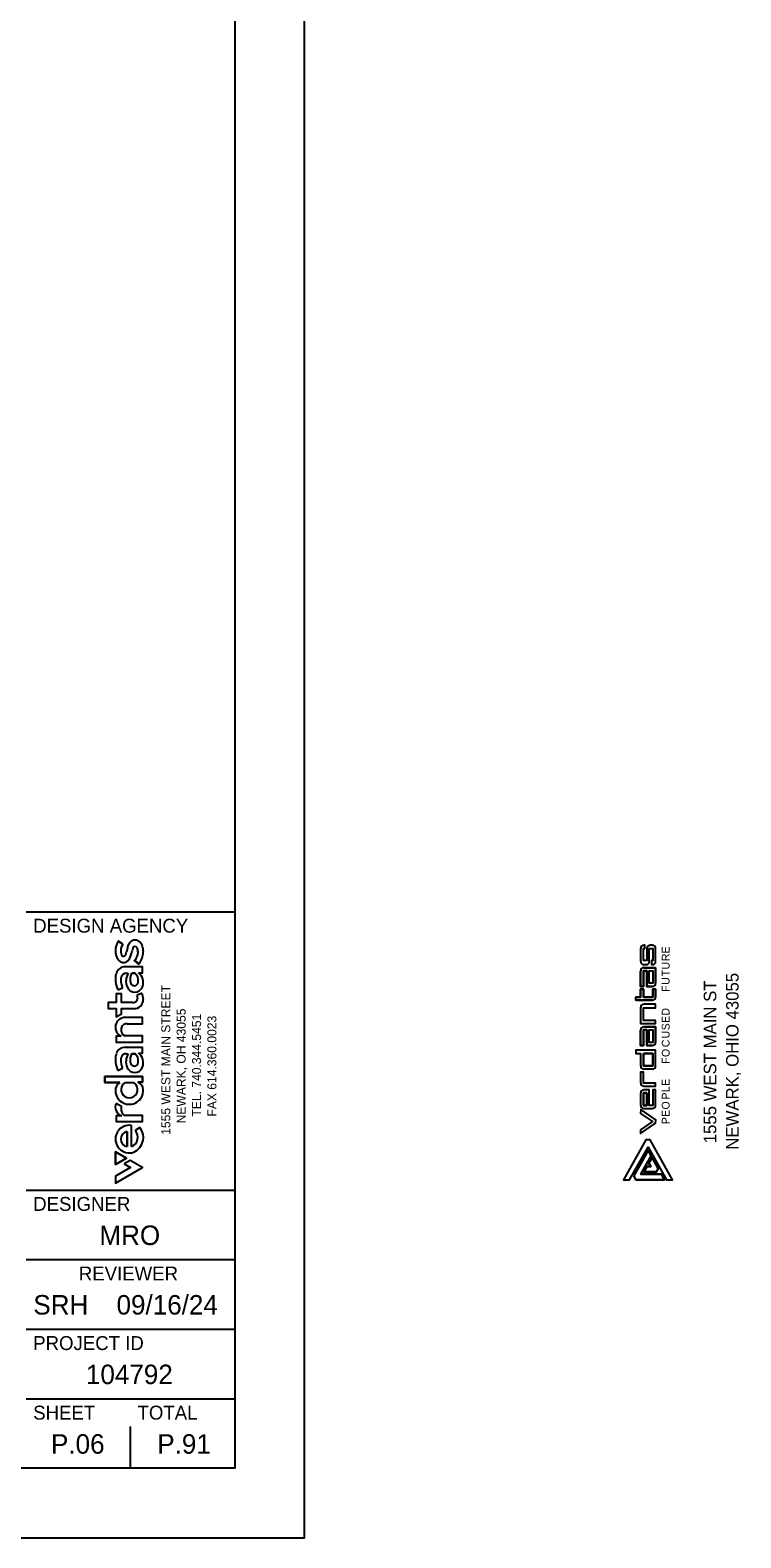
# Model space of a CAD drawing. Extents: x 0 to 37.1, y 0 to 22.
# Drawn here: x 32.03 to 37.14, y 0 to 10.84 of the extents above; entities that cross this region are included whole.
import ezdxf

# ---------------------------------------------------------------- set-up
doc = ezdxf.new("R2010")
doc.units = 0
for name, color, linetype in [('CS-ANNO-TTLB-LOGO', 7, 'Continuous'), ('Default', 7, 'Continuous'), ('SH_Border', 7, 'Continuous'), ('SH_Cut_Line', 7, 'Continuous'), ('SH_Data', 7, 'Continuous'), ('SH_Text', 7, 'Continuous')]:
    doc.layers.add(name, color=color, linetype=linetype)

msp = doc.modelspace()

# ---------------------------------------------------------------- linework, layer by layer
at = {"layer": 'CS-ANNO-TTLB-LOGO'}
for p, q in [((36.417, 4.236), (36.417, 4.143)), ((36.448, 4.259), (36.44, 4.259)), ((36.502, 4.259), (36.485, 4.259)), ((36.524, 4.143), (36.524, 4.236)), ((36.44, 4.121), (36.457, 4.121)), ((36.417, 3.963), (36.417, 4.076)), ((36.417, 3.539), (36.417, 3.651)), ((36.44, 3.37), (36.502, 3.37)), ((36.417, 3.198), (36.417, 3.108)), ((36.524, 3.108), (36.524, 3.221)), ((36.44, 3.086), (36.502, 3.086))]:
    msp.add_line(p, q, dxfattribs=at)
for points in [[(36.462, 4.236), (36.462, 4.149), (36.437, 4.149), (36.437, 4.236), (36.448, 4.236), (36.448, 4.259)], [(36.479, 4.143), (36.479, 4.236), (36.504, 4.236), (36.504, 4.149), (36.496, 4.149), (36.496, 4.121), (36.502, 4.121)], [(36.502, 3.963), (36.462, 3.963), (36.462, 4.076), (36.437, 4.076), (36.437, 3.963), (36.417, 3.963)], [(36.44, 4.098), (36.524, 4.098), (36.524, 3.986)], [(36.383, 3.887), (36.417, 3.887), (36.417, 3.944), (36.437, 3.944), (36.437, 3.887), (36.504, 3.887), (36.504, 3.944), (36.524, 3.944), (36.524, 3.887)], [(36.502, 3.865), (36.383, 3.865), (36.383, 3.887)], [(36.417, 3.814), (36.417, 3.696), (36.524, 3.696), (36.524, 3.719), (36.437, 3.719), (36.437, 3.809), (36.524, 3.809)], [(36.524, 3.809), (36.524, 3.837), (36.44, 3.837)], [(36.502, 3.539), (36.462, 3.539), (36.462, 3.651), (36.437, 3.651), (36.437, 3.539), (36.417, 3.539)], [(36.44, 3.674), (36.524, 3.674), (36.524, 3.561)], [(36.383, 3.505), (36.383, 3.482), (36.417, 3.482), (36.417, 3.392)], [(36.524, 3.392), (36.524, 3.505), (36.383, 3.505)], [(36.524, 3.269), (36.437, 3.269), (36.437, 3.347), (36.417, 3.347), (36.417, 3.269)], [(36.44, 3.246), (36.524, 3.246), (36.524, 3.269)], [(36.524, 3.221), (36.504, 3.221), (36.504, 3.108), (36.479, 3.108), (36.479, 3.221), (36.44, 3.221)]]:
    msp.add_lwpolyline(points, dxfattribs=at)
for points in [[(36.479, 4.076), (36.504, 4.076), (36.504, 3.986), (36.479, 3.986)], [(36.479, 3.651), (36.504, 3.651), (36.504, 3.561), (36.479, 3.561)], [(36.437, 3.482), (36.437, 3.392), (36.504, 3.392), (36.504, 3.482)], [(36.462, 3.198), (36.437, 3.198), (36.437, 3.108), (36.462, 3.108)], [(36.502, 2.992), (36.417, 2.933), (36.417, 2.906), (36.524, 2.98), (36.525, 3.004), (36.418, 3.078), (36.417, 3.051)]]:
    msp.add_lwpolyline(points, close=True, dxfattribs=at)
for centre, start, end in [((36.44, 4.236), 90, 180), ((36.485, 4.236), 90, 180), ((36.502, 4.236), 360, 90), ((36.44, 4.143), 180, 270), ((36.457, 4.143), 270, 0), ((36.502, 4.143), 270, 0), ((36.44, 4.076), 90, 180), ((36.502, 3.986), 270, 360), ((36.44, 3.814), 90, 180), ((36.502, 3.887), 270, 360), ((36.44, 3.651), 90, 180), ((36.502, 3.561), 270, 360), ((36.44, 3.392), 180, 270), ((36.502, 3.392), 270, 0), ((36.44, 3.269), 180, 270), ((36.44, 3.198), 90, 180), ((36.44, 3.108), 180, 270), ((36.502, 3.108), 270, 0)]:
    msp.add_arc(centre, 0.0225, start, end, dxfattribs=at)
at = {"layer": 'Default'}
for p, q in [((36.417, 4.236), (36.417, 4.143)), ((36.502, 4.259), (36.485, 4.259)), ((36.524, 4.143), (36.524, 4.236)), ((36.44, 4.121), (36.457, 4.121)), ((36.44, 3.37), (36.502, 3.37)), ((36.417, 3.198), (36.417, 3.108)), ((36.44, 3.086), (36.502, 3.086)), ((36.367, 2.602), (36.47, 2.785)), ((36.493, 2.745), (36.419, 2.614)), ((36.47, 2.785), (36.493, 2.745)), ((36.382, 2.574), (36.367, 2.602)), ((36.419, 2.614), (36.567, 2.614)), ((36.567, 2.614), (36.589, 2.574)), ((36.589, 2.574), (36.382, 2.574))]:
    msp.add_line(p, q, dxfattribs=at)
for points in [[(36.462, 4.236), (36.462, 4.149), (36.437, 4.149), (36.437, 4.236), (36.448, 4.236), (36.448, 4.259), (36.44, 4.259)], [(36.479, 4.143), (36.479, 4.236), (36.504, 4.236), (36.504, 4.149), (36.496, 4.149), (36.496, 4.121), (36.502, 4.121)], [(36.417, 4.076), (36.417, 3.963), (36.437, 3.963), (36.437, 4.076), (36.462, 4.076), (36.462, 3.963), (36.502, 3.963)], [(36.524, 3.986), (36.524, 4.098), (36.44, 4.098)], [(36.524, 3.887), (36.524, 3.944), (36.504, 3.944), (36.504, 3.887), (36.437, 3.887), (36.437, 3.944), (36.417, 3.944), (36.417, 3.887), (36.383, 3.887), (36.383, 3.865), (36.502, 3.865)], [(36.417, 3.814), (36.417, 3.696), (36.524, 3.696), (36.524, 3.719), (36.437, 3.719), (36.437, 3.809), (36.524, 3.809), (36.524, 3.837), (36.44, 3.837)], [(36.417, 3.651), (36.417, 3.539), (36.437, 3.539), (36.437, 3.651), (36.462, 3.651), (36.462, 3.539), (36.502, 3.539)], [(36.524, 3.561), (36.524, 3.674), (36.44, 3.674)], [(36.524, 3.392), (36.524, 3.505), (36.383, 3.505), (36.383, 3.482), (36.417, 3.482), (36.417, 3.392)], [(36.44, 3.246), (36.524, 3.246), (36.524, 3.269), (36.437, 3.269), (36.437, 3.347), (36.417, 3.347), (36.417, 3.269)], [(36.524, 3.108), (36.524, 3.221), (36.504, 3.221), (36.504, 3.108), (36.479, 3.108), (36.479, 3.221), (36.44, 3.221)]]:
    msp.add_lwpolyline(points, dxfattribs=at)
for points in [[(36.504, 4.076), (36.504, 3.986), (36.479, 3.986), (36.479, 4.076)], [(36.504, 3.651), (36.504, 3.561), (36.479, 3.561), (36.479, 3.651)], [(36.437, 3.482), (36.504, 3.482), (36.504, 3.392), (36.437, 3.392)], [(36.462, 3.198), (36.462, 3.108), (36.437, 3.108), (36.437, 3.198)], [(36.417, 2.933), (36.417, 2.906), (36.524, 2.98), (36.525, 3.004), (36.418, 3.078), (36.417, 3.051), (36.502, 2.992)], [(36.47, 2.808), (36.602, 2.574), (36.647, 2.574), (36.486, 2.86), (36.454, 2.86), (36.293, 2.574), (36.338, 2.574)], [(36.338, 2.574), (36.47, 2.808), (36.602, 2.574), (36.647, 2.574), (36.486, 2.86), (36.454, 2.86), (36.293, 2.574)], [(36.367, 2.602), (36.382, 2.574), (36.589, 2.574), (36.567, 2.614), (36.419, 2.614), (36.493, 2.745), (36.47, 2.785)], [(36.463, 2.67), (36.441, 2.631), (36.531, 2.631), (36.544, 2.654), (36.499, 2.734), (36.477, 2.694), (36.49, 2.67)], [(36.463, 2.67), (36.49, 2.67), (36.477, 2.694), (36.499, 2.734), (36.544, 2.654), (36.531, 2.631), (36.441, 2.631)]]:
    msp.add_lwpolyline(points, close=True, dxfattribs=at)
for centre, start, end in [((36.44, 4.236), 90, 180), ((36.485, 4.236), 90, 180), ((36.502, 4.236), 360, 90), ((36.44, 4.143), 180, 270), ((36.457, 4.143), 270, 0), ((36.502, 4.143), 270, 0), ((36.44, 4.076), 90, 180), ((36.502, 3.986), 270, 0), ((36.44, 3.814), 90, 180), ((36.502, 3.887), 270, 0), ((36.44, 3.651), 90, 180), ((36.502, 3.561), 270, 0), ((36.44, 3.392), 180, 270), ((36.502, 3.392), 270, 0), ((36.44, 3.269), 180, 270), ((36.44, 3.198), 90, 180), ((36.44, 3.108), 180, 270), ((36.502, 3.108), 270, 0)]:
    msp.add_arc(centre, 0.0225, start, end, dxfattribs=at)
at = {"layer": 'SH_Border'}
for p, q in [((32, 4.5), (33.5, 4.5)), ((32, 2.5), (33.5, 2.5)), ((32, 2), (33.5, 2)), ((32, 1.5), (33.5, 1.5)), ((32, 1), (33.5, 1))]:
    msp.add_line(p, q, dxfattribs=at)
msp.add_lwpolyline([(1.5, 21.5), (33.5, 21.5), (33.5, 0.5), (1.5, 0.5)], close=True, dxfattribs=at)
at = {"layer": 'SH_Cut_Line'}
msp.add_lwpolyline([(0, 0), (34, 0), (34, 22), (0, 22)], close=True, dxfattribs=at)
at = {"layer": 'SH_Data'}
for p, q in [((32.75, 3.5), (32.75, 3.5)), ((32.75, 0.5), (32.75, 0.8)), ((32.375, 0.675), (32.375, 0.675))]:
    msp.add_line(p, q, dxfattribs=at)
at = {"layer": 'SH_Text'}
for p, q in [((32.693, 4.267), (32.662, 4.29)), ((32.727, 4.241), (32.721, 4.21)), ((32.757, 4.199), (32.761, 4.219)), ((32.779, 4.151), (32.812, 4.127)), ((32.717, 4.058), (32.733, 4.058)), ((32.758, 4.058), (32.781, 4.058)), ((32.653, 3.951), (32.658, 3.939)), ((32.83, 3.915), (32.795, 3.899)), ((32.717, 3.48), (32.733, 3.48)), ((32.758, 3.48), (32.781, 3.48)), ((32.653, 3.372), (32.658, 3.36)), ((32.711, 3.272), (32.771, 3.272)), ((32.684, 3.1), (32.647, 3.123)), ((32.756, 2.812), (32.756, 2.965)), ((32.816, 2.95), (32.783, 2.928)), ((32.726, 2.92), (32.726, 2.813))]:
    msp.add_line(p, q, dxfattribs=at)
for points in [[(32.695, 4.269), (32.663, 4.292), (32.662, 4.29)], [(32.693, 4.267), (32.695, 4.269)], [(32.727, 4.241), (32.721, 4.21)], [(32.757, 4.199), (32.761, 4.219)], [(32.779, 4.151), (32.777, 4.149), (32.808, 4.124), (32.812, 4.127)], [(32.806, 4.062), (32.836, 4.062), (32.836, 4.104), (32.711, 4.104)], [(32.806, 4.062), (32.836, 4.062), (32.836, 4.104), (32.711, 4.104)], [(32.717, 4.058), (32.733, 4.058)], [(32.781, 4.058), (32.758, 4.058)], [(32.767, 3.849), (32.685, 3.849), (32.685, 3.91), (32.646, 3.91), (32.646, 3.849), (32.588, 3.849), (32.588, 3.804), (32.646, 3.804), (32.646, 3.744), (32.685, 3.767), (32.685, 3.804), (32.775, 3.804)], [(32.767, 3.849), (32.685, 3.849), (32.685, 3.91), (32.646, 3.91), (32.646, 3.849), (32.588, 3.849), (32.588, 3.804), (32.646, 3.804), (32.646, 3.744), (32.685, 3.767), (32.685, 3.804), (32.775, 3.804)], [(32.653, 3.951), (32.658, 3.939)], [(32.658, 3.939), (32.693, 3.953), (32.689, 3.962)], [(32.658, 3.939), (32.693, 3.953), (32.689, 3.962)], [(32.83, 3.915), (32.795, 3.899)], [(32.725, 3.695), (32.836, 3.695), (32.836, 3.74), (32.712, 3.74)], [(32.725, 3.695), (32.836, 3.695), (32.836, 3.74), (32.712, 3.74)], [(32.683, 3.605), (32.646, 3.605), (32.646, 3.563), (32.836, 3.563), (32.836, 3.609), (32.709, 3.609)], [(32.683, 3.605), (32.646, 3.605), (32.646, 3.563), (32.836, 3.563), (32.836, 3.609), (32.709, 3.609)], [(32.806, 3.484), (32.836, 3.484), (32.836, 3.525), (32.711, 3.525)], [(32.806, 3.484), (32.836, 3.484), (32.836, 3.525), (32.711, 3.525)], [(32.717, 3.48), (32.733, 3.48)], [(32.781, 3.48), (32.758, 3.48)], [(32.653, 3.372), (32.658, 3.36)], [(32.658, 3.36), (32.693, 3.375), (32.689, 3.384)], [(32.658, 3.36), (32.693, 3.375), (32.689, 3.384)], [(32.672, 3.272), (32.565, 3.272), (32.565, 3.317), (32.836, 3.317), (32.836, 3.276), (32.803, 3.276)], [(32.803, 3.276), (32.836, 3.276), (32.836, 3.317), (32.565, 3.317), (32.565, 3.272), (32.672, 3.272)], [(32.711, 3.272), (32.771, 3.272)], [(32.687, 3.033), (32.646, 3.033), (32.646, 2.992), (32.836, 2.992), (32.836, 3.036), (32.71, 3.036)], [(32.687, 3.033), (32.646, 3.033), (32.646, 2.992), (32.836, 2.992), (32.836, 3.036), (32.71, 3.036)], [(32.684, 3.1), (32.647, 3.123)], [(32.756, 2.812), (32.756, 2.965)], [(32.816, 2.95), (32.783, 2.928)], [(32.726, 2.813), (32.726, 2.92)], [(32.641, 2.775), (32.641, 2.684), (32.72, 2.73), (32.641, 2.775)], [(32.705, 2.688), (32.749, 2.662), (32.641, 2.6), (32.641, 2.55), (32.836, 2.662), (32.748, 2.713), (32.705, 2.688)]]:
    msp.add_lwpolyline(points, dxfattribs=at)
for points in [[(32.72, 2.73), (32.641, 2.684), (32.641, 2.775)], [(32.705, 2.688), (32.749, 2.662), (32.641, 2.6), (32.641, 2.55), (32.836, 2.662), (32.748, 2.713)]]:
    msp.add_lwpolyline(points, close=True, dxfattribs=at)
for centre, radius, start, end in [((32.772, 4.219), 0.131, 147.2233, 179.842), ((32.772, 4.219), 0.131, 147.2233, 179.842), ((32.774, 4.216), 0.0948, 148.1233, 178.1135), ((32.774, 4.216), 0.0948, 148.1233, 178.1135), ((32.854, 4.212), 0.13, 154.0447, 167.2149), ((32.854, 4.212), 0.13, 154.0447, 167.2149), ((32.782, 4.247), 0.0493, 52.7092, 154.2166), ((32.782, 4.247), 0.0493, 52.7092, 154.2166), ((32.855, 4.203), 0.0949, 158.1863, 170.6328), ((32.855, 4.203), 0.0949, 158.1863, 170.6328), ((32.782, 4.234), 0.0165, 26.9165, 163.602), ((32.782, 4.234), 0.0165, 26.9165, 163.602), ((32.738, 4.213), 0.0655, 357.0077, 26.3112), ((32.738, 4.213), 0.0655, 357.0077, 26.3112), ((32.767, 4.232), 0.0711, 22.8278, 50.7157), ((32.767, 4.232), 0.0711, 22.8278, 50.7157), ((32.722, 4.213), 0.12, 359.0192, 22.9257), ((32.722, 4.213), 0.12, 359.0192, 22.9257), ((32.755, 4.218), 0.114, 179.0109, 203.56), ((32.755, 4.218), 0.114, 179.0109, 203.56), ((32.712, 4.199), 0.067, 203.3692, 237.807), ((32.712, 4.199), 0.067, 203.3692, 237.807), ((32.7, 4.181), 0.0458, 238.9453, 317.6829), ((32.7, 4.181), 0.0458, 238.9453, 317.6829), ((32.749, 4.218), 0.0702, 179.0539, 195.6921), ((32.749, 4.218), 0.0702, 179.0539, 195.6921), ((32.714, 4.207), 0.0335, 193.8561, 223.7191), ((32.714, 4.207), 0.0335, 193.8561, 223.7191), ((32.7, 4.195), 0.0148, 224.7822, 330.4366), ((32.7, 4.195), 0.0148, 224.7822, 330.4366), ((32.64, 4.225), 0.0819, 332.9002, 349.3831), ((32.64, 4.225), 0.0819, 332.9002, 349.3831), ((32.653, 4.218), 0.105, 320.1259, 349.7023), ((32.653, 4.218), 0.105, 320.1259, 349.7023), ((32.711, 4.214), 0.0932, 317.363, 356.9244), ((32.711, 4.214), 0.0932, 317.363, 356.9244), ((32.712, 4.21), 0.129, 320.5166, 0.4341), ((32.712, 4.21), 0.129, 320.5166, 0.4341), ((32.769, 4.017), 0.128, 160.8128, 180.9317), ((32.769, 4.017), 0.128, 160.8128, 180.9317), ((32.84, 4.018), 0.199, 180.9467, 199.8354), ((32.84, 4.018), 0.199, 180.9467, 199.8354), ((32.709, 4.04), 0.0639, 88.076, 162.8642), ((32.709, 4.04), 0.0639, 88.076, 162.8642), ((32.744, 4.012), 0.0647, 163.2522, 179.9971), ((32.744, 4.012), 0.0647, 163.2522, 179.9971), ((32.831, 4.016), 0.152, 181.6616, 200.8714), ((32.831, 4.016), 0.152, 181.6616, 200.8714), ((32.719, 4.021), 0.0374, 92.9671, 165.223), ((32.719, 4.021), 0.0374, 92.9671, 165.223), ((32.825, 4.002), 0.108, 148.3497, 202.4708), ((32.825, 4.002), 0.108, 148.3497, 202.4708), ((32.852, 4.012), 0.105, 153.8372, 188.8746), ((32.852, 4.012), 0.105, 153.8372, 188.8746), ((32.742, 4.008), 0.0637, 348.1247, 52.3678), ((32.742, 4.008), 0.0637, 348.1247, 52.3678), ((32.756, 3.993), 0.0857, 338.2774, 53.7949), ((32.756, 3.993), 0.0857, 338.2774, 53.7949), ((32.78, 3.982), 0.0592, 201.6764, 339.7268), ((32.78, 3.982), 0.0592, 201.6764, 339.7268), ((32.777, 3.997), 0.0281, 182.327, 355.3778), ((32.777, 3.997), 0.0281, 182.327, 355.3778), ((32.748, 3.87), 0.0939, 359.5424, 28.2495), ((32.748, 3.87), 0.0939, 359.5424, 28.2495), ((32.77, 3.88), 0.0314, 265.0692, 356.3548), ((32.77, 3.88), 0.0314, 265.0692, 356.3548), ((32.777, 3.868), 0.0642, 267.8641, 1.6213), ((32.777, 3.868), 0.0642, 267.8641, 1.6213), ((32.758, 3.877), 0.0432, 1.8638, 29.9651), ((32.758, 3.877), 0.0432, 1.8638, 29.9651), ((32.711, 3.67), 0.0703, 88.9896, 246.9111), ((32.711, 3.67), 0.0703, 88.9896, 246.9111), ((32.723, 3.652), 0.0433, 86.9739, 132.7421), ((32.723, 3.652), 0.0433, 86.9739, 132.7421), ((32.725, 3.654), 0.0434, 137.3049, 182.9688), ((32.725, 3.654), 0.0434, 137.3049, 182.9688), ((32.729, 3.652), 0.0477, 180.3466, 244.9113), ((32.729, 3.652), 0.0477, 180.3466, 244.9113), ((32.769, 3.438), 0.128, 160.8128, 180.9317), ((32.769, 3.438), 0.128, 160.8128, 180.9317), ((32.709, 3.462), 0.0639, 88.076, 162.8642), ((32.709, 3.462), 0.0639, 88.076, 162.8642), ((32.719, 3.443), 0.0374, 92.9671, 165.223), ((32.719, 3.443), 0.0374, 92.9671, 165.223), ((32.825, 3.423), 0.108, 148.3497, 202.4708), ((32.825, 3.423), 0.108, 148.3497, 202.4708), ((32.852, 3.434), 0.105, 153.8372, 188.8746), ((32.852, 3.434), 0.105, 153.8372, 188.8746), ((32.742, 3.43), 0.0637, 348.1247, 52.3678), ((32.742, 3.43), 0.0637, 348.1247, 52.3678), ((32.756, 3.415), 0.0857, 338.2774, 53.7949), ((32.756, 3.415), 0.0857, 338.2774, 53.7949), ((32.84, 3.439), 0.199, 180.9467, 199.8354), ((32.84, 3.439), 0.199, 180.9467, 199.8354), ((32.744, 3.434), 0.0647, 163.2522, 179.9971), ((32.744, 3.434), 0.0647, 163.2522, 179.9971), ((32.831, 3.438), 0.152, 181.6616, 200.8714), ((32.831, 3.438), 0.152, 181.6616, 200.8714), ((32.78, 3.403), 0.0592, 201.6764, 339.7268), ((32.78, 3.403), 0.0592, 201.6764, 339.7268), ((32.777, 3.419), 0.0281, 182.327, 355.3778), ((32.777, 3.419), 0.0281, 182.327, 355.3778), ((32.712, 3.213), 0.0714, 124.2843, 181.2723), ((32.712, 3.213), 0.0714, 124.2843, 181.2723), ((32.74, 3.221), 0.0586, 119.9007, 175.5797), ((32.74, 3.221), 0.0586, 119.9007, 175.5797), ((32.742, 3.221), 0.0588, 6.0666, 60.041), ((32.742, 3.221), 0.0588, 6.0666, 60.041), ((32.774, 3.215), 0.0671, 5.3084, 64.5252), ((32.774, 3.215), 0.0671, 5.3084, 64.5252), ((32.741, 3.216), 0.1, 182.7719, 2.9779), ((32.741, 3.216), 0.1, 182.7719, 2.9779), ((32.741, 3.222), 0.0595, 176.4529, 5.055), ((32.741, 3.222), 0.0595, 176.4529, 5.055), ((32.703, 3.094), 0.0628, 152.6524, 255.2929), ((32.703, 3.094), 0.0628, 152.6524, 255.2929), ((32.736, 3.084), 0.0545, 162.1384, 242.0408), ((32.736, 3.084), 0.0545, 162.1384, 242.0408), ((32.741, 2.866), 0.0996, 81.0446, 280.2577), ((32.741, 2.866), 0.0996, 81.0446, 280.2577), ((32.73, 2.879), 0.072, 290.9232, 42.7391), ((32.73, 2.879), 0.072, 290.9232, 42.7391), ((32.728, 2.878), 0.114, 285.6668, 39.3699), ((32.728, 2.878), 0.114, 285.6668, 39.3699), ((32.734, 2.866), 0.0543, 98.8378, 261.1622), ((32.734, 2.866), 0.0543, 98.8378, 261.1622)]:
    msp.add_arc(centre, radius, start, end, dxfattribs=at)

# ---------------------------------------------------------------- texts
at = {"layer": 'Default'}
for s, p in [('E', (36.625, 4.201)), ('R', (36.625, 4.146)), ('U', (36.625, 4.085)), ('T', (36.625, 4.036)), ('U', (36.625, 3.975)), ('F', (36.625, 3.924)), ('D', (36.625, 3.754)), ('S', (36.625, 3.648)), ('E', (36.625, 3.701)), ('C', (36.625, 3.527)), ('U', (36.625, 3.59)), ('O', (36.625, 3.456)), ('F', (36.625, 3.407)), ('E', (36.625, 3.249)), ('L', (36.625, 3.203)), ('P', (36.625, 3.151)), ('O', (36.625, 3.079)), ('E', (36.625, 3.026)), ('P', (36.625, 2.974))]:
    msp.add_text(s, height=0.0563, rotation=90, dxfattribs=at).set_placement(p)
at = {"layer": 'SH_Data'}
for s, height, p in [('DESIGN AGENCY', 0.1, (32.05, 4.35)), ('DESIGNER', 0.1, (32.05, 2.35)), ('MRO', 0.14, (32.526, 2.105)), ('REVIEWER', 0.1, (32.378, 1.85)), ('SRH', 0.14, (32.051, 1.605)), ('09/16/24', 0.14, (32.649, 1.605)), ('PROJECT ID', 0.1, (32.05, 1.35)), ('104792', 0.14, (32.429, 1.105)), ('SHEET', 0.1, (32.05, 0.85)), ('TOTAL', 0.1, (32.8, 0.85)), ('P.06', 0.14, (32.178, 0.605)), ('P.91', 0.14, (32.942, 0.605))]:
    msp.add_text(s, height=height, dxfattribs=at).set_placement(p)
at = {"layer": 'SH_Text'}
for s, height, p in [('NEWARK, OHIO 43055', 0.09, (37.121, 2.79)), ('1555 WEST MAIN STREET', 0.06497, (33.036, 2.897)), ('1555 WEST MAIN ST', 0.09, (36.961, 2.836)), ('NEWARK, OH 43055', 0.06497, (33.146, 2.979)), ('TEL. 740.344.5451', 0.06497, (33.257, 3.028)), ('FAX 614.360.0023', 0.06497, (33.367, 3.028))]:
    msp.add_text(s, height=height, rotation=90, dxfattribs=at).set_placement(p)

doc.saveas('drawing.dxf')
